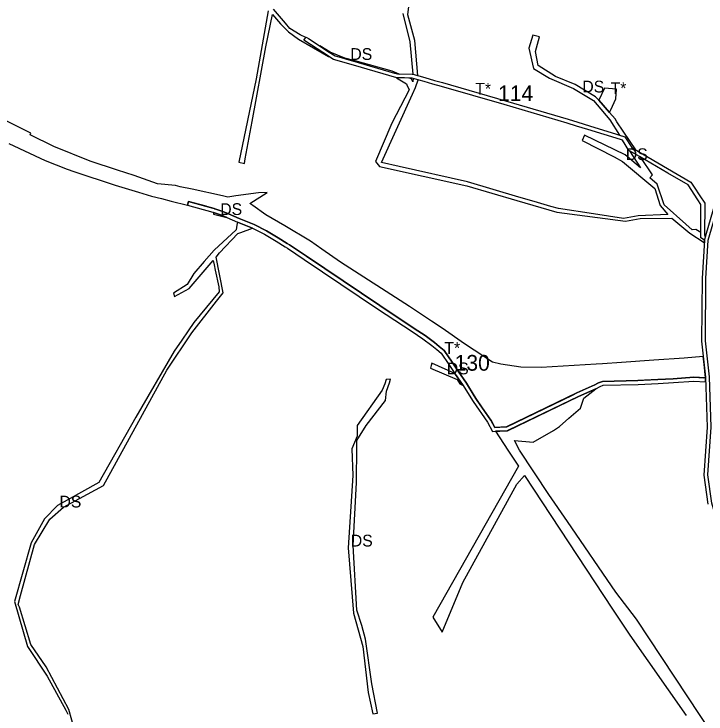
# Model space of a CAD drawing. Extents: x -477304 to -465641, y -1159113 to -1149285.
# Drawn here: x -472121 to -471593, y -1153843 to -1153308 of the extents above; entities that cross this region are included whole.
import ezdxf

# ---------------------------------------------------------------- set-up
doc = ezdxf.new("R2010")
doc.units = 0
for name, color, linetype in [('17', 7, 'Continuous'), ('35', 7, 'Continuous'), ('4', 7, 'Continuous'), ('60', 7, 'Continuous')]:
    doc.layers.add(name, color=color, linetype=linetype)

msp = doc.modelspace()

# ---------------------------------------------------------------- linework, layer by layer
at = {"layer": '17'}
for p, q in [((-471670.26, -1153364.73), (-471674.44, -1153373.77)), ((-471660.98, -1153365.44), (-471670.26, -1153364.73)), ((-471674.44, -1153373.77), (-471666.26, -1153383.35)), ((-471666.26, -1153383.35), (-471665.29, -1153381.16))]:
    msp.add_line(p, q, dxfattribs=at)
msp.add_lwpolyline([(-471665.29, -1153381.16), (-471661.65, -1153372.95), (-471660.98, -1153365.44)], dxfattribs=at)
at = {"layer": '35'}
for p, q in [((-471913.74, -1153315.09), (-471922.97, -1153304.32)), ((-471927.02, -1153305.64), (-471936.35, -1153357.54)), ((-471928.89, -1153333.01), (-471923.82, -1153308.31)), ((-471923.82, -1153308.31), (-471917.58, -1153315.57)), ((-471824.15, -1153307.75), (-471818.75, -1153329.23)), ((-471815.07, -1153328.39), (-471820.29, -1153308.71)), ((-471917.58, -1153315.57), (-471916.52, -1153316.64)), ((-471910.4, -1153318.98), (-471913.74, -1153315.09)), ((-471916.52, -1153316.64), (-471911.57, -1153321.64)), ((-471902.61, -1153323.85), (-471910.4, -1153318.98)), ((-471898.37, -1153325.98), (-471902.61, -1153323.85)), ((-471899.76, -1153328.14), (-471898.37, -1153325.98)), ((-471724.88, -1153324.13), (-471727.91, -1153334.02)), ((-471719.91, -1153325.45), (-471724.88, -1153324.13)), ((-471722.79, -1153336.72), (-471719.91, -1153325.45)), ((-471880.19, -1153340.78), (-471899.76, -1153328.14)), ((-471818.75, -1153329.23), (-471816.55, -1153354.01)), ((-471812.78, -1153355.09), (-471815.07, -1153328.39)), ((-471939.37, -1153390.08), (-471928.89, -1153333.01)), ((-471879.78, -1153337.12), (-471887.7, -1153332.36)), ((-471868.56, -1153341.7), (-471879.78, -1153337.12)), ((-471720.94, -1153347.37), (-471722.79, -1153336.72)), ((-471881.08, -1153340.44), (-471880.19, -1153340.78)), ((-471860.66, -1153343.89), (-471868.56, -1153341.7)), ((-471832.35, -1153351.73), (-471860.66, -1153343.89)), ((-471707.66, -1153355.84), (-471720.94, -1153347.37)), ((-471827.01, -1153353.87), (-471832.35, -1153351.73)), ((-471936.35, -1153357.54), (-471949.54, -1153421.33)), ((-471829, -1153356.76), (-471821.45, -1153361.35)), ((-471817.57, -1153357.66), (-471819.34, -1153356.95)), ((-471816.54, -1153359.88), (-471817.57, -1153357.66)), ((-471816.55, -1153354.01), (-471812.78, -1153355.09)), ((-471816.31, -1153357.2), (-471816.54, -1153359.88)), ((-471812.62, -1153358.25), (-471816.31, -1153357.2)), ((-471814.51, -1153364.07), (-471812.62, -1153358.25)), ((-471692.54, -1153361.8), (-471707.66, -1153355.84)), ((-471821.45, -1153361.35), (-471821.04, -1153362.25)), ((-471821.04, -1153362.25), (-471819.33, -1153366.05)), ((-471676.96, -1153371.18), (-471692.54, -1153361.8)), ((-471819.33, -1153366.05), (-471832.54, -1153391.52)), ((-471816.9, -1153369.35), (-471814.51, -1153364.07)), ((-471840.51, -1153421.4), (-471816.9, -1153369.35)), ((-471678.48, -1153374.22), (-471675.88, -1153377.32)), ((-471674.44, -1153373.77), (-471676.96, -1153371.18)), ((-471666.26, -1153383.35), (-471674.44, -1153373.77)), ((-471675.88, -1153377.32), (-471666.11, -1153388.94)), ((-472108.28, -1153399.08), (-472129.3, -1153388.74)), ((-471944.64, -1153418.78), (-471939.37, -1153390.08)), ((-471666.11, -1153388.94), (-471658.72, -1153400.51)), ((-471646.32, -1153411.83), (-471660.68, -1153390.36)), ((-472108.95, -1153400.24), (-472108.28, -1153399.08)), ((-472090.72, -1153409.29), (-472108.95, -1153400.24)), ((-471685.34, -1153400.65), (-471687.15, -1153404.69)), ((-472063.06, -1153420.36), (-472090.72, -1153409.29)), ((-471651.04, -1153412.55), (-471642.77, -1153425.5)), ((-472042.22, -1153427.26), (-472063.06, -1153420.36)), ((-471949.54, -1153421.33), (-471945.26, -1153422.17)), ((-471945.26, -1153422.17), (-471944.64, -1153418.78)), ((-471827.12, -1153424.41), (-471840.51, -1153421.4)), ((-471656.33, -1153420.69), (-471631.77, -1153441.45)), ((-471633.52, -1153430.97), (-471642.52, -1153417.52)), ((-472029.35, -1153431.46), (-472042.22, -1153427.26)), ((-471842.15, -1153424.45), (-471775.43, -1153439.26)), ((-471774.86, -1153436.18), (-471827.12, -1153424.41)), ((-472011.63, -1153437.7), (-472029.35, -1153431.46)), ((-471635.45, -1153433.1), (-471633.52, -1153430.97)), ((-471629.96, -1153438.07), (-471635.45, -1153433.1)), ((-472043.89, -1153438.68), (-472025.97, -1153444.13)), ((-471997.81, -1153439.11), (-472011.63, -1153437.7)), ((-471624.68, -1153453.77), (-471629.96, -1153438.07)), ((-472025.97, -1153444.13), (-472016.13, -1153447.13)), ((-471994.34, -1153439.95), (-471997.81, -1153439.11)), ((-471985.12, -1153441.92), (-471994.34, -1153439.95)), ((-471961.88, -1153446.89), (-471985.12, -1153441.92)), ((-471775.43, -1153439.26), (-471737.06, -1153450.39)), ((-471631.77, -1153441.45), (-471627.6, -1153454.28)), ((-472016.13, -1153447.13), (-472008.45, -1153448.85)), ((-472008.45, -1153448.85), (-472001.03, -1153450.88)), ((-471957.87, -1153447.89), (-471961.88, -1153446.89)), ((-471951.8, -1153447.02), (-471957.87, -1153447.89)), ((-471934.5, -1153444.55), (-471951.8, -1153447.02)), ((-471941.12, -1153452.76), (-471927.83, -1153444.38)), ((-471927.83, -1153444.38), (-471934.5, -1153444.55)), ((-472001.03, -1153450.88), (-471988.67, -1153454.16)), ((-471988.67, -1153454.16), (-471987.87, -1153451.27)), ((-471974.31, -1153454.91), (-471987.87, -1153451.27)), ((-471987.87, -1153451.27), (-471969.38, -1153456.36)), ((-471938.69, -1153454.41), (-471941.12, -1153452.76)), ((-471928.85, -1153461.55), (-471938.69, -1153454.41)), ((-471737.06, -1153450.39), (-471706.61, -1153459.35)), ((-471627.6, -1153454.28), (-471621.89, -1153461.11)), ((-471608.11, -1153468.55), (-471624.68, -1153453.77)), ((-471968.76, -1153459.67), (-471968.78, -1153460.84)), ((-471705.24, -1153456.69), (-471711.29, -1153454.96)), ((-471706.61, -1153459.35), (-471654.16, -1153466.33)), ((-471678.5, -1153460.6), (-471705.24, -1153456.69)), ((-471968.78, -1153460.84), (-471958.52, -1153463.47)), ((-471919.16, -1153467.06), (-471928.85, -1153461.55)), ((-471655.79, -1153464.23), (-471678.5, -1153460.6)), ((-471654.16, -1153466.33), (-471643.06, -1153464.25)), ((-471643.06, -1153464.25), (-471618.64, -1153463.91)), ((-471618.64, -1153463.91), (-471608.08, -1153472.99)), ((-471950.93, -1153469.41), (-471951.59, -1153472.94)), ((-471950.47, -1153466.99), (-471950.93, -1153469.41)), ((-471939.11, -1153471.66), (-471950.47, -1153466.99)), ((-471914.42, -1153469.76), (-471919.16, -1153467.06)), ((-471894.64, -1153481.51), (-471914.42, -1153469.76)), ((-471603.31, -1153472.83), (-471608.11, -1153468.55)), ((-471951.59, -1153472.94), (-471968.31, -1153488.34)), ((-471964.29, -1153490.57), (-471950.19, -1153475.63)), ((-471950.19, -1153475.63), (-471948.05, -1153474.9)), ((-471948.05, -1153474.9), (-471939.11, -1153471.66)), ((-471608.08, -1153472.99), (-471605.05, -1153475.41)), ((-471605.05, -1153475.41), (-471594, -1153482.53)), ((-471600.43, -1153472.68), (-471603.31, -1153472.83)), ((-471596.7, -1153474.97), (-471600.43, -1153472.68)), ((-471886.12, -1153487.55), (-471894.64, -1153481.51)), ((-471594, -1153482.53), (-471593.89, -1153480.75)), ((-471593, -1153477.24), (-471593.71, -1153476.81)), ((-471968.31, -1153488.34), (-471975.9, -1153497.16)), ((-471966.75, -1153493.81), (-471964.29, -1153490.57)), ((-471871.81, -1153497.68), (-471886.12, -1153487.55)), ((-471987.44, -1153517.83), (-471969.07, -1153496.41)), ((-471975.9, -1153497.16), (-471983.74, -1153506.28)), ((-471969.07, -1153496.41), (-471968.34, -1153499.61)), ((-471961.43, -1153521.05), (-471966.75, -1153493.81)), ((-471968.34, -1153499.61), (-471967.49, -1153503.67)), ((-471819.13, -1153531.58), (-471871.81, -1153497.68)), ((-471983.74, -1153506.28), (-471988.88, -1153514.66)), ((-471967.49, -1153503.67), (-471964.85, -1153516.31)), ((-471998.49, -1153523.72), (-471987.44, -1153517.83)), ((-471964.85, -1153516.31), (-471964.48, -1153520.38)), ((-471964.48, -1153520.38), (-471983.88, -1153543.59)), ((-471966.58, -1153527.48), (-471961.43, -1153521.05)), ((-471985.25, -1153551.54), (-471966.58, -1153527.48)), ((-471794.14, -1153548.03), (-471802.2, -1153542.72)), ((-471777, -1153559.89), (-471794.14, -1153548.03)), ((-472004.36, -1153580.21), (-471985.25, -1153551.54)), ((-471755.61, -1153573.99), (-471777, -1153559.89)), ((-471609.34, -1153570.92), (-471632.6, -1153572.54)), ((-471594.82, -1153569.69), (-471609.34, -1153570.92)), ((-471594.42, -1153573.4), (-471594.82, -1153569.69)), ((-471802.59, -1153576.53), (-471803.18, -1153578.69)), ((-471802.11, -1153574.79), (-471802.59, -1153576.53)), ((-471784.37, -1153582.56), (-471802.11, -1153574.79)), ((-471749.41, -1153575.55), (-471755.61, -1153573.99)), ((-471734.18, -1153577.82), (-471749.41, -1153575.55)), ((-471671.73, -1153575.21), (-471676.48, -1153575.51)), ((-471657.21, -1153574.25), (-471671.73, -1153575.21)), ((-471632.6, -1153572.54), (-471657.21, -1153574.25)), ((-471593.63, -1153580.51), (-471594.42, -1153573.4)), ((-472023.03, -1153613.97), (-472004.36, -1153580.21)), ((-471803.18, -1153578.69), (-471782.82, -1153587.25)), ((-471778.06, -1153591.77), (-471784.37, -1153582.56)), ((-471593.26, -1153583.91), (-471593.63, -1153580.51)), ((-471594.62, -1153585.87), (-471593.1, -1153585.33)), ((-471593.1, -1153585.33), (-471593.26, -1153583.91)), ((-471838.04, -1153590.46), (-471840.01, -1153595.31)), ((-471691.34, -1153597.43), (-471678.82, -1153591.88)), ((-471840.01, -1153595.31), (-471859.03, -1153622.31)), ((-471837.44, -1153603.19), (-471836.64, -1153596.16)), ((-471744.73, -1153623.31), (-471694.74, -1153599.07)), ((-471694.74, -1153599.07), (-471691.34, -1153597.43)), ((-471676.83, -1153594.28), (-471690.08, -1153600.15)), ((-471685.88, -1153601.51), (-471676.83, -1153594.28)), ((-471768, -1153602.46), (-471764.13, -1153607.98)), ((-471690.08, -1153600.15), (-471743.41, -1153626)), ((-471688.63, -1153609.17), (-471685.88, -1153601.51)), ((-471693.89, -1153613.68), (-471688.63, -1153609.17)), ((-472052.89, -1153668.3), (-472023.03, -1153613.97)), ((-472028.25, -1153616.11), (-472056.43, -1153665.87)), ((-471859.03, -1153622.31), (-471859.15, -1153630.6)), ((-471709.18, -1153626.07), (-471704.46, -1153623.06)), ((-471859.15, -1153630.6), (-471863.18, -1153640.14)), ((-471752.16, -1153626.72), (-471753.43, -1153626.77)), ((-471753.43, -1153626.77), (-471743.9, -1153641.24)), ((-471744.19, -1153626.38), (-471752.16, -1153626.72)), ((-471743.41, -1153626), (-471744.19, -1153626.38)), ((-471724.65, -1153635.09), (-471709.18, -1153626.07)), ((-471734.99, -1153641.27), (-471739.05, -1153633.72)), ((-471739.05, -1153633.72), (-471724.65, -1153635.09)), ((-471743.9, -1153641.24), (-471735.93, -1153653.33)), ((-471712.61, -1153674.97), (-471734.99, -1153641.27)), ((-471735.93, -1153653.33), (-471801.34, -1153768.87)), ((-471731.23, -1153660.47), (-471663.98, -1153762.6)), ((-472083.35, -1153684.75), (-472052.89, -1153668.3)), ((-472056.43, -1153665.87), (-472080.68, -1153679.5)), ((-472093.7, -1153693.92), (-472083.35, -1153684.75)), ((-472097.89, -1153693.74), (-472108.14, -1153711.89)), ((-472108.14, -1153711.89), (-472120.67, -1153756.88)), ((-471865.86, -1153715.68), (-471862.01, -1153765.72)), ((-471794.14, -1153780.14), (-471778.44, -1153742.23)), ((-472117.95, -1153759.06), (-472116.11, -1153752.19)), ((-472120.67, -1153756.88), (-472110.74, -1153791.15)), ((-471663.98, -1153762.6), (-471650.86, -1153782.52)), ((-471801.34, -1153768.87), (-471794.14, -1153780.14)), ((-471650.86, -1153782.52), (-471607.91, -1153843.77)), ((-472110.74, -1153791.15), (-472095.9, -1153813.94)), ((-472079.23, -1153839.2), (-472096.66, -1153806.67)), ((-472095.9, -1153813.94), (-472081.69, -1153839.79)), ((-472081.69, -1153839.79), (-472080.08, -1153842.87)), ((-472071.24, -1153867.68), (-472079.23, -1153839.2))]:
    msp.add_line(p, q, dxfattribs=at)
for points in [[(-471820.29, -1153308.71), (-471818.89, -1153296.06), (-471801.22, -1153283.99)], [(-471911.57, -1153321.64), (-471904.01, -1153327.22), (-471881.08, -1153340.44)], [(-471887.7, -1153332.36), (-471880.4, -1153337.07), (-471880.36, -1153337.1), (-471875.91, -1153339.97), (-471871.38, -1153341.29), (-471871.38, -1153341.29), (-471867.88, -1153342.31), (-471865.57, -1153342.99)], [(-471727.91, -1153334.02), (-471724.47, -1153349.55), (-471712.31, -1153357.11)], [(-471865.57, -1153342.99), (-471860.97, -1153344.33), (-471858.26, -1153345.11), (-471830.67, -1153353.15), (-471828.23, -1153353.86), (-471827.01, -1153353.87)], [(-471819.34, -1153356.95), (-471822.84, -1153356.91), (-471828.67, -1153356.86), (-471829, -1153356.76)], [(-471712.31, -1153357.11), (-471693.89, -1153365.01), (-471678.48, -1153374.22)], [(-471660.68, -1153390.36), (-471662.14, -1153388.18), (-471666.26, -1153383.35)], [(-471832.54, -1153391.52), (-471844.98, -1153420.64), (-471842.15, -1153424.45)], [(-471642.77, -1153425.5), (-471654.33, -1153415.61), (-471685.34, -1153400.65)], [(-471658.72, -1153400.51), (-471654.58, -1153401.78), (-471649.4, -1153410.03), (-471647.3, -1153411.26), (-471646.32, -1153411.83)], [(-471687.15, -1153404.69), (-471662.86, -1153417.07), (-471656.33, -1153420.69)], [(-472125.12, -1153406.85), (-472097.37, -1153419.96), (-472080.49, -1153426.52)], [(-471642.52, -1153417.52), (-471643.47, -1153416.96), (-471651.04, -1153412.55)], [(-472080.49, -1153426.52), (-472075.51, -1153428.45), (-472043.89, -1153438.68)], [(-471711.29, -1153454.96), (-471723.92, -1153451.35), (-471735.56, -1153448.02), (-471774.86, -1153436.18)], [(-471987.87, -1153451.27), (-471987.87, -1153451.27), (-471974.31, -1153454.91)], [(-471969.38, -1153456.36), (-471968.4, -1153456.63), (-471967.94, -1153456.78)], [(-471958.52, -1153463.47), (-471962.75, -1153461.68), (-471968.76, -1153459.67)], [(-471967.94, -1153456.78), (-471967.81, -1153456.82), (-471961.69, -1153458.87), (-471957.33, -1153460.71), (-471949.3, -1153464.23), (-471937.87, -1153468.93), (-471928.38, -1153473.68), (-471919.52, -1153479), (-471912.44, -1153483.26), (-471910.78, -1153484.26), (-471897.82, -1153492.96), (-471841.9, -1153530.68), (-471815.5, -1153548.15), (-471807.26, -1153553.59), (-471800.13, -1153558.96), (-471796.42, -1153562.08), (-471792.66, -1153565.15), (-471786.61, -1153573.97), (-471781.9, -1153580.86), (-471775.54, -1153590.14), (-471769.8, -1153599.58), (-471768, -1153602.46)], [(-471621.89, -1153461.11), (-471644.45, -1153462.09), (-471655.79, -1153464.23)], [(-471596.71, -1153477.67), (-471596.7, -1153475.32), (-471596.7, -1153474.97)], [(-471593.89, -1153480.75), (-471596.72, -1153479), (-471596.71, -1153477.84), (-471596.71, -1153477.67)], [(-471593.71, -1153476.81), (-471593.71, -1153477.11), (-471593.71, -1153477.33), (-471593.13, -1153477.69)], [(-471593.13, -1153477.69), (-471593.07, -1153477.49), (-471593, -1153477.24)], [(-471988.88, -1153514.66), (-471999.48, -1153521.18), (-471998.49, -1153523.72)], [(-471802.2, -1153542.72), (-471815.38, -1153534.05), (-471819.13, -1153531.58)], [(-471983.88, -1153543.59), (-471988.24, -1153550.1), (-471993.1, -1153557.1), (-471998.93, -1153565.49), (-472028.25, -1153616.11)], [(-471676.48, -1153575.51), (-471718.53, -1153578.15), (-471734.18, -1153577.82)], [(-471836.64, -1153596.16), (-471834.42, -1153589.88), (-471833.52, -1153587), (-471837, -1153587.17), (-471838.04, -1153590.46)], [(-471782.82, -1153587.25), (-471780.55, -1153590.53), (-471778.06, -1153591.77)], [(-471678.82, -1153591.88), (-471678.13, -1153591.58), (-471674.7, -1153589.79), (-471671.82, -1153588.68), (-471644.69, -1153588), (-471640.42, -1153587.78)], [(-471640.42, -1153587.78), (-471629.44, -1153587.22), (-471617.63, -1153586.63), (-471602.02, -1153585.46), (-471594.62, -1153585.87)], [(-471859.27, -1153638.3), (-471859.32, -1153633.69), (-471852.32, -1153622.43), (-471837.44, -1153603.19)], [(-471764.13, -1153607.98), (-471756.9, -1153618.26), (-471756.53, -1153618.95)], [(-471704.46, -1153623.06), (-471697.46, -1153616.82), (-471693.89, -1153613.68)], [(-471756.53, -1153618.95), (-471753.92, -1153623.79), (-471746.23, -1153623.46)], [(-471746.23, -1153623.46), (-471744.94, -1153623.41), (-471744.73, -1153623.31)], [(-471863.18, -1153640.14), (-471862.48, -1153660.6), (-471865.86, -1153715.68)], [(-471862.07, -1153713.9), (-471859.62, -1153665.83), (-471859.27, -1153638.3)], [(-471778.44, -1153742.23), (-471737.17, -1153667.13), (-471731.23, -1153660.47)], [(-471661.65, -1153749.74), (-471698.53, -1153695.64), (-471712.61, -1153674.97)], [(-472080.68, -1153679.5), (-472087.83, -1153683.48), (-472097.89, -1153693.74)], [(-472116.11, -1153752.19), (-472105.64, -1153713.21), (-472093.7, -1153693.92)], [(-471862.01, -1153765.72), (-471854.71, -1153791.16), (-471850.57, -1153826.42), (-471847.13, -1153842.59), (-471843.63, -1153842.18), (-471847.89, -1153819.79), (-471852.73, -1153785.61), (-471855.53, -1153775.02), (-471859.32, -1153763.4), (-471862.07, -1153713.9)], [(-471555.79, -1153912.87), (-471567.88, -1153888.17), (-471645.83, -1153770.38), (-471661.65, -1153749.74)], [(-472096.66, -1153806.67), (-472108.39, -1153789.57), (-472116.91, -1153761.16), (-472117.95, -1153759.06)]]:
    msp.add_lwpolyline(points, dxfattribs=at)
at = {"layer": '4'}
for p, q in [((-471987.87, -1153451.27), (-471988.67, -1153454.16)), ((-471592.97, -1153588.96), (-471593.08, -1153585.95))]:
    msp.add_line(p, q, dxfattribs=at)
for points in [[(-471880.36, -1153337.1), (-471875.91, -1153339.97), (-471871.38, -1153341.29), (-471871.38, -1153341.29), (-471867.88, -1153342.31), (-471860.97, -1153344.33), (-471858.26, -1153345.11), (-471830.67, -1153353.15), (-471828.23, -1153353.86), (-471817.05, -1153353.97), (-471816.69, -1153353.97), (-471812.01, -1153355.3), (-471807.3, -1153356.64), (-471800.08, -1153358.7), (-471793.96, -1153360.44), (-471745.91, -1153374.31), (-471697.95, -1153388.48), (-471690.57, -1153390.74), (-471681.67, -1153393.47), (-471661.01, -1153399.81), (-471654.58, -1153401.78), (-471649.4, -1153410.03), (-471647.3, -1153411.26), (-471604.23, -1153436.37), (-471601.74, -1153440.2), (-471597.4, -1153446.86), (-471593.63, -1153452.65), (-471593.71, -1153477.11), (-471593.71, -1153477.33), (-471593.13, -1153477.69), (-471593.89, -1153480.32), (-471593.89, -1153480.75), (-471596.72, -1153479), (-471596.71, -1153477.84), (-471596.7, -1153475.32), (-471596.63, -1153453.54), (-471598.94, -1153449.99), (-471606.36, -1153438.6), (-471621.74, -1153429.63), (-471643.47, -1153416.96), (-471651.55, -1153412.25), (-471656.53, -1153404.32), (-471657.9, -1153403.9), (-471682.79, -1153396.27), (-471691.53, -1153393.59), (-471698.81, -1153391.35), (-471746.75, -1153377.19), (-471794.78, -1153363.33), (-471801.19, -1153361.5), (-471808.01, -1153359.56), (-471811.81, -1153358.48), (-471817, -1153357), (-471817.13, -1153356.97), (-471822.84, -1153356.91), (-471828.67, -1153356.86), (-471861.81, -1153347.21), (-471877.14, -1153342.74), (-471877.18, -1153342.73), (-471899.76, -1153328.14), (-471898.34, -1153325.94), (-471898.14, -1153325.62), (-471896.26, -1153326.83), (-471880.4, -1153337.07), (-471880.36, -1153337.1)], [(-471518.29, -1153956.42), (-471540.25, -1153885.85), (-471527.35, -1153830.76), (-471528.58, -1153824.83), (-471547.09, -1153784.31), (-471550.09, -1153776.39), (-471556.65, -1153756.83), (-471579.89, -1153709.91), (-471588.26, -1153681.79), (-471591.27, -1153660.08), (-471588.75, -1153623.57), (-471590.11, -1153585.11), (-471593.12, -1153557.74), (-471592.67, -1153510.14), (-471590.89, -1153480.85), (-471590.89, -1153480.76), (-471571.76, -1153414.78), (-471284.73, -1153493.73), (-471221.49, -1153401.29), (-471197.08, -1153396.57), (-471170.8, -1153425.91), (-471167.61, -1153429.48)], [(-471573.82, -1153411.1), (-471593.07, -1153477.49), (-471593.13, -1153477.69), (-471593.89, -1153480.32), (-471593.89, -1153480.75), (-471595.67, -1153510.03), (-471596.12, -1153557.89), (-471593.1, -1153585.33), (-471591.75, -1153623.52), (-471594.28, -1153660.18), (-471591.2, -1153682.43)], [(-471988.67, -1153454.16), (-471969.27, -1153459.5), (-471968.76, -1153459.67), (-471962.75, -1153461.68), (-471958.52, -1153463.47), (-471950.47, -1153466.99), (-471939.11, -1153471.66), (-471929.83, -1153476.31), (-471921.07, -1153481.57), (-471913.99, -1153485.83), (-471912.39, -1153486.79), (-471899.49, -1153495.45), (-471843.57, -1153533.17), (-471817.15, -1153550.65), (-471808.99, -1153556.04), (-471802, -1153561.31), (-471798.33, -1153564.39), (-471794.89, -1153567.2), (-471789.09, -1153575.67), (-471784.37, -1153582.56), (-471778.06, -1153591.77), (-471772.35, -1153601.15), (-471770.5, -1153604.12)], [(-471768, -1153602.46), (-471769.8, -1153599.58), (-471775.54, -1153590.14), (-471781.9, -1153580.86), (-471786.61, -1153573.97), (-471792.66, -1153565.15), (-471796.42, -1153562.08), (-471800.13, -1153558.96), (-471807.26, -1153553.59), (-471815.5, -1153548.15), (-471841.9, -1153530.68), (-471897.82, -1153492.96), (-471910.78, -1153484.26), (-471912.44, -1153483.26), (-471919.52, -1153479), (-471928.38, -1153473.68), (-471937.87, -1153468.93), (-471949.3, -1153464.23), (-471957.33, -1153460.71), (-471961.69, -1153458.87), (-471967.81, -1153456.82), (-471968.4, -1153456.63), (-471987.87, -1153451.27)], [(-471770.5, -1153604.12), (-471759.46, -1153619.84), (-471755.67, -1153626.87), (-471744.19, -1153626.38), (-471690.08, -1153600.15), (-471676.83, -1153594.28), (-471673.47, -1153592.53), (-471671.23, -1153591.67), (-471644.58, -1153591), (-471629.29, -1153590.22), (-471617.44, -1153589.62), (-471601.99, -1153588.47), (-471592.97, -1153588.96)], [(-471593.08, -1153585.95), (-471602.02, -1153585.46), (-471617.63, -1153586.63), (-471629.44, -1153587.22), (-471644.69, -1153588), (-471671.82, -1153588.68), (-471674.7, -1153589.79), (-471678.13, -1153591.58), (-471691.34, -1153597.43), (-471744.94, -1153623.41), (-471753.92, -1153623.79), (-471756.9, -1153618.26), (-471768, -1153602.46)]]:
    msp.add_lwpolyline(points, dxfattribs=at)

# ---------------------------------------------------------------- texts
at = {"layer": '17'}
msp.add_text('T*', height=9, dxfattribs=at).set_placement((-471665.52, -1153369.23))
at = {"layer": '35'}
for p in [(-471864.29, -1153343.12), (-471687.12, -1153367.98), (-471653.92, -1153419.64), (-471963.65, -1153461.57), (-471790.62, -1153583.28), (-472086.46, -1153684.98), (-471863.91, -1153714.79)]:
    msp.add_text('DS', height=9, dxfattribs=at).set_placement(p)
at = {"layer": '4'}
for p in [(-471768.87, -1153369.63), (-471792.47, -1153567.7)]:
    msp.add_text('T*', height=9, dxfattribs=at).set_placement(p)
at = {"layer": '60'}
for s, p in [('114', (-471751.42, -1153374.61)), ('130', (-471784.59, -1153580.49))]:
    msp.add_text(s, height=12, dxfattribs=at).set_placement(p)

doc.saveas('drawing.dxf')
